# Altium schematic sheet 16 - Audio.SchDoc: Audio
size A3; PageSetup: Record=PageOptions¦CenterHorizontal=True¦CenterVertical=True¦PrintScale=0.70¦XCorrection=1.00¦YCorrection=1.00¦PrintKind=0¦BorderSize=5000000¦LeftOffset=0¦BottomOffset=0¦Orientation=2¦PaperLength=4200¦PaperWidth=2970¦Scale=100¦PaperSource=7¦PrintQuality=600¦MediaType=1¦DitherType=10¦PaperKind=A4¦PrintScaleMode=1; Author: Juan Anzola; SheetNumber: 16; SheetTotal: 20
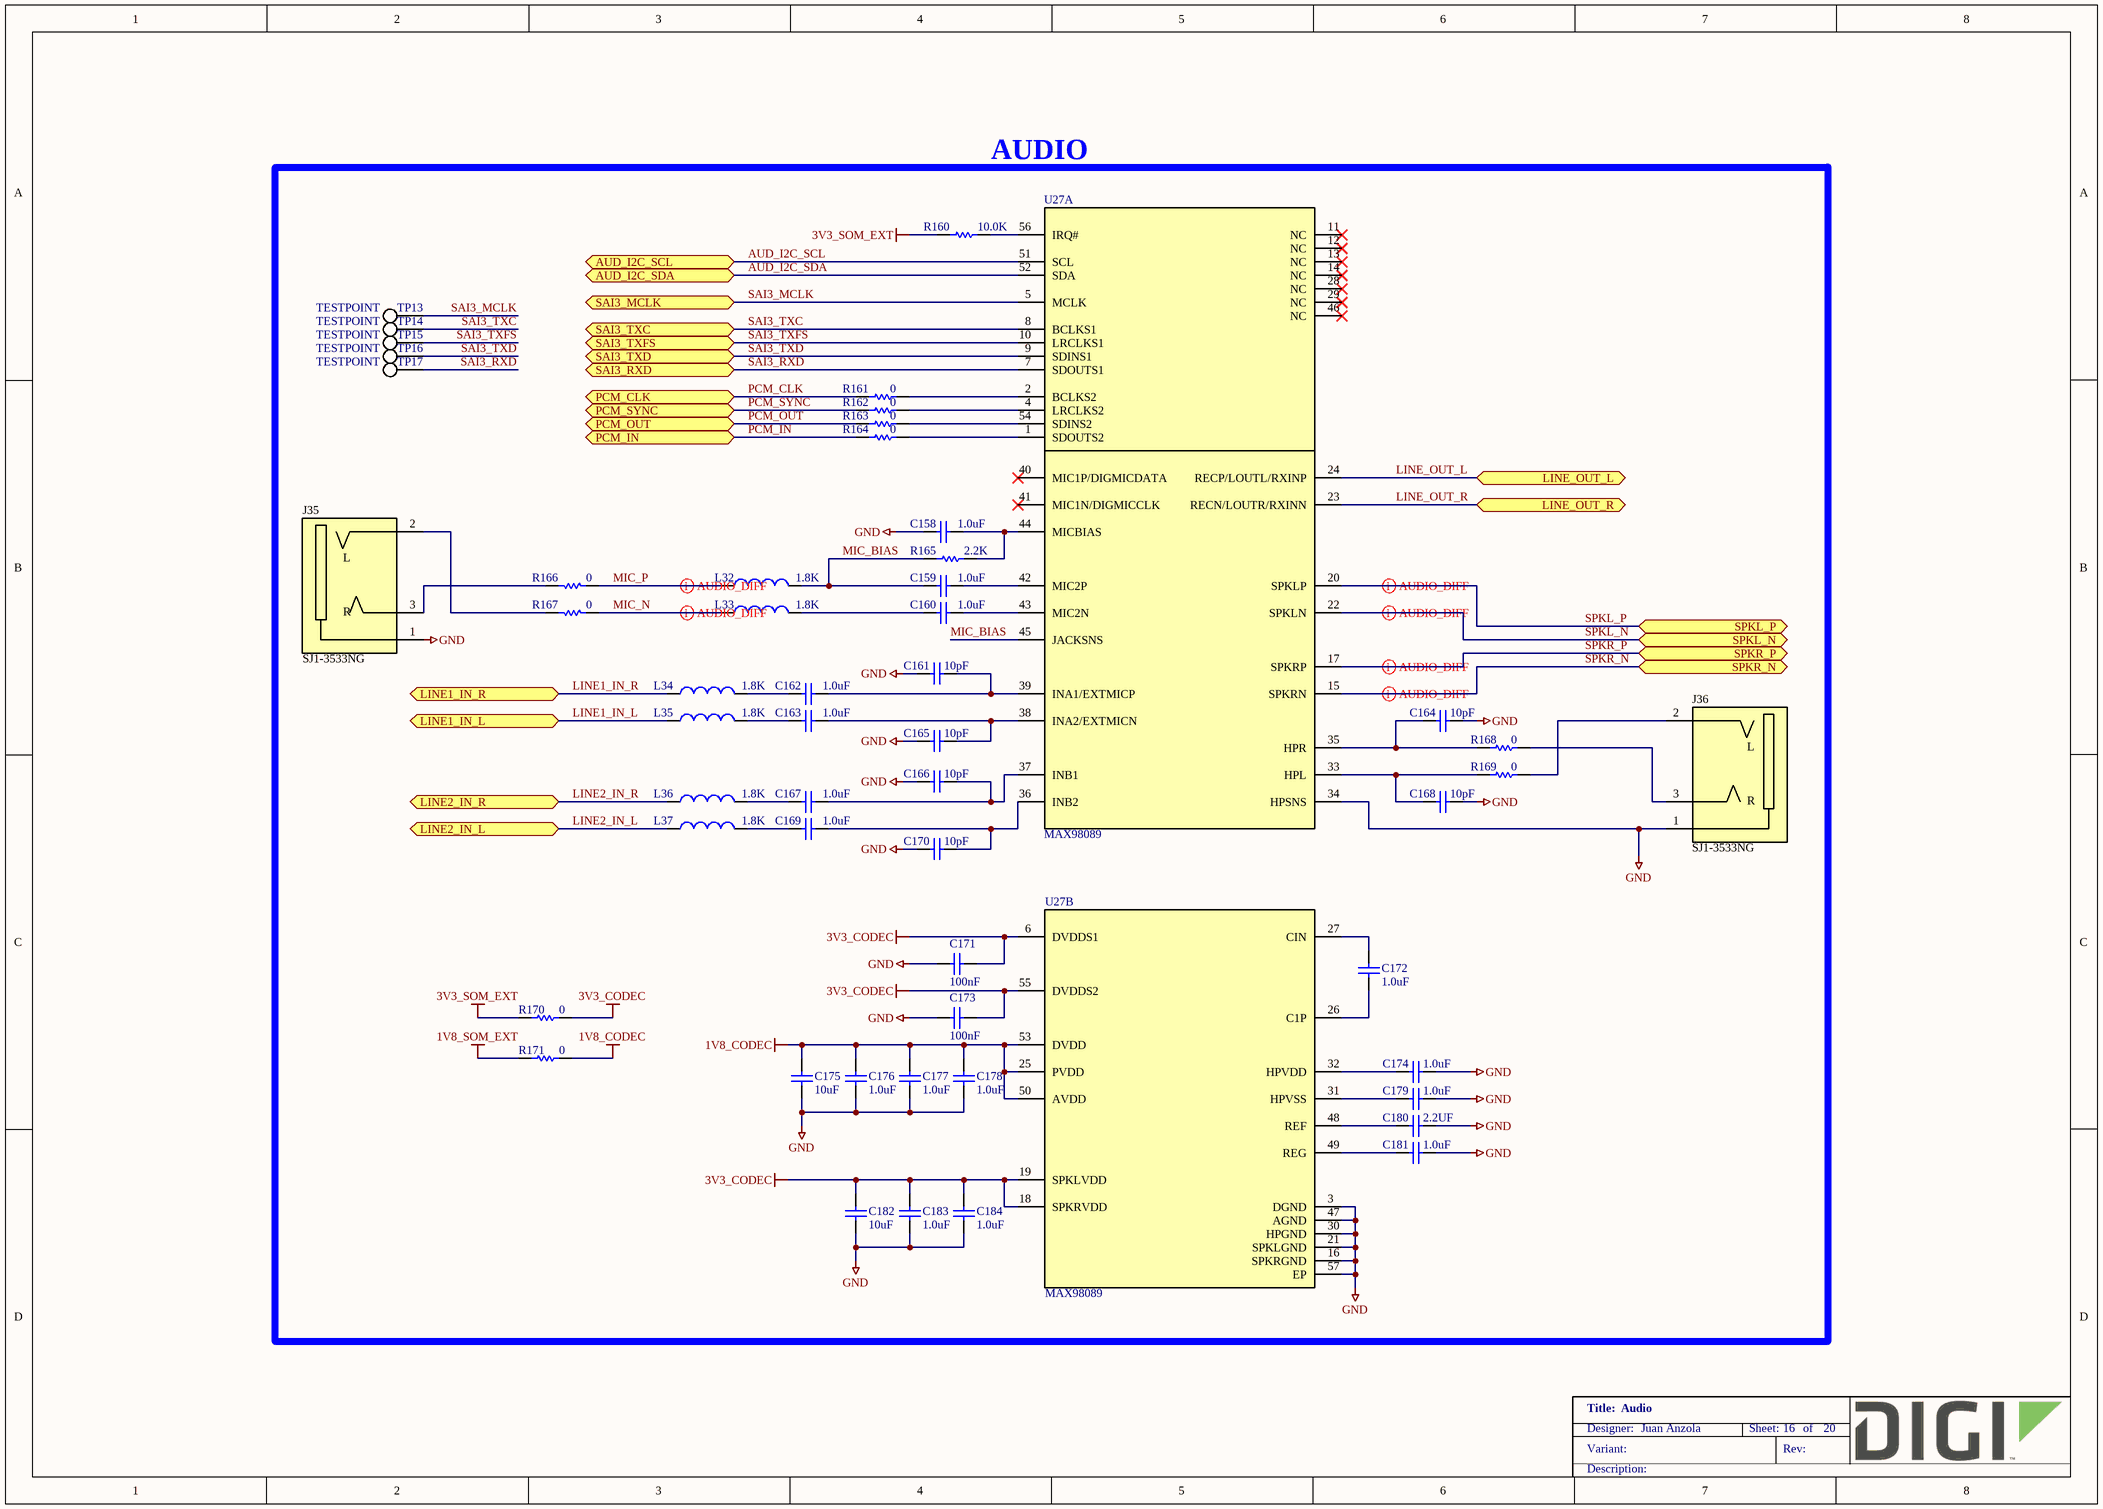
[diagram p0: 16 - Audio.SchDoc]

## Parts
C158  1.0uF  [CAPC1005X55N]
C159  1.0uF  [CAPC1005X55N]
C160  1.0uF  [CAPC1005X55N]
C161  10pF  [CAPC1005X55N]
C162  1.0uF  [CAPC1005X55N]
C163  1.0uF  [CAPC1005X55N]
C164  10pF  [CAPC1005X55N]
C165  10pF  [CAPC1005X55N]
C166  10pF  [CAPC1005X55N]
C167  1.0uF  [CAPC1005X55N]
C168  10pF  [CAPC1005X55N]
C169  1.0uF  [CAPC1005X55N]
C170  10pF  [CAPC1005X55N]
C171  100nF  [CAPC1005X55N]
C172  1.0uF  [CAPC1005X55N]
C173  100nF  [CAPC1005X55N]
C174  1.0uF  [CAPC1005X55N]
C175  10uF  [CAPC1005X55N]
C176  1.0uF  [CAPC1005X55N]
C177  1.0uF  [CAPC1005X55N]
C178  1.0uF  [CAPC1005X55N]
C179  1.0uF  [CAPC1005X55N]
C180  2.2UF  [CAPC1608X90N]
C181  1.0uF  [CAPC1005X55N]
C182  10uF  [CAPC1005X55N]
C183  1.0uF  [CAPC1005X55N]
C184  1.0uF  [CAPC1005X55N]
J35  SJ1-3533NG  [CUI_SJ1-3533N]
J36  SJ1-3533NG  [CUI_SJ1-3533N]
L32  1.8K  [INDC1005X60N]
L33  1.8K  [INDC1005X60N]
L34  1.8K  [INDC1005X60N]
L35  1.8K  [INDC1005X60N]
L36  1.8K  [INDC1005X60N]
L37  1.8K  [INDC1005X60N]
R160  10.0K  [RESC1005X40N]
R161  0  [RESC1005X40N]
R162  0  [RESC1005X40N]
R163  0  [RESC1005X40N]
R164  0  [RESC1005X40N]
R165  2.2K  [RESC1005X40N]
R166  0  [RESC1005X40N]
R167  0  [RESC1005X40N]
R168  0  [RESC1005X40N]
R169  0  [RESC1005X40N]
R170  0  [RESC1609X55N]
R171  0  [RESC1609X55N]
TP13  TESTPOINT  [TP0762]  (no BOM)
TP14  TESTPOINT  [TP0762]  (no BOM)
TP15  TESTPOINT  [TP0762]  (no BOM)
TP16  TESTPOINT  [TP0762]  (no BOM)
TP17  TESTPOINT  [TP0762]  (no BOM)
U27  MAX98089  [QFN40P700X700X80-57T560X560N]  (parts A,B of 2)

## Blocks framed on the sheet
AUDIO: C158-C184 J35 J36 L32-L37 R160-R171 TP13-TP17 U27

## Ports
AUD_I2C_SCL (bidir), AUD_I2C_SDA (bidir), LINE1_IN_L (bidir), LINE1_IN_R (bidir), LINE2_IN_L (bidir), LINE2_IN_R (bidir), LINE_OUT_L (bidir), LINE_OUT_R (bidir), PCM_CLK (bidir), PCM_IN (bidir), PCM_OUT (bidir), PCM_SYNC (bidir), SAI3_MCLK (bidir), SAI3_RXD (bidir), SAI3_TXC (bidir), SAI3_TXD (bidir), SAI3_TXFS (bidir), SPKL_N (bidir), SPKL_P (bidir), SPKR_N (bidir), SPKR_P (bidir)

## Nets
1V8_CODEC: C175.2 C176.1 C177.1 C178.1 R171.2 U27.25(PVDD) U27.50(AVDD) U27.53(DVDD)
1V8_SOM_EXT: R171.1
3V3_CODEC: C171.2 C173.2 C182.2 C183.1 C184.1 R170.2 U27.6(DVDDS1) U27.18(SPKRVDD) U27.19(SPKLVDD) U27.55(DVDDS2)
3V3_SOM_EXT: R160.1 R170.1
GND: C158.2 C161.2 C164.2 C165.2 C166.2 C168.2 C170.2 C171.1 C173.1 C174.1 C175.1 C176.2 C177.2 C178.2 C179.1 C180.1 C181.1 C182.1 C183.2 C184.2 J35.1 J36.1 U27.3(DGND) U27.16(SPKRGND) U27.21(SPKLGND) U27.30(HPGND) U27.34(HPSNS) U27.47(AGND) U27.57(EP)
AUD_I2C_SCL: U27.51(SCL) ; port AUD_I2C_SCL
AUD_I2C_SDA: U27.52(SDA) ; port AUD_I2C_SDA
LINE1_IN_L: L35.1 ; port LINE1_IN_L
LINE1_IN_R: L34.1 ; port LINE1_IN_R
LINE2_IN_L: L37.1 ; port LINE2_IN_L
LINE2_IN_R: L36.1 ; port LINE2_IN_R
LINE_OUT_L: U27.24(RECP/LOUTL/RXINP) ; port LINE_OUT_L
LINE_OUT_R: U27.23(RECN/LOUTR/RXINN) ; port LINE_OUT_R
MIC_BIAS: C159.2 L32.2 R165.1 U27.45(JACKSNS)
MIC_N: L33.1 R167.1
MIC_P: L32.1 R166.1
PCM_CLK: R161.1 ; port PCM_CLK
PCM_IN: R164.1 ; port PCM_IN
PCM_OUT: R163.1 ; port PCM_OUT
PCM_SYNC: R162.1 ; port PCM_SYNC
SAI3_MCLK: TP13.1 U27.5(MCLK) ; port SAI3_MCLK
SAI3_RXD: TP17.1 U27.7(SDOUTS1) ; port SAI3_RXD
SAI3_TXC: TP14.1 U27.8(BCLKS1) ; port SAI3_TXC
SAI3_TXD: TP16.1 U27.9(SDINS1) ; port SAI3_TXD
SAI3_TXFS: TP15.1 U27.10(LRCLKS1) ; port SAI3_TXFS
SPKL_N: U27.22(SPKLN) ; port SPKL_N
SPKL_P: U27.20(SPKLP) ; port SPKL_P
SPKR_N: U27.15(SPKRN) ; port SPKR_N
SPKR_P: U27.17(SPKRP) ; port SPKR_P
NetC158_1: C158.1 R165.2 U27.44(MICBIAS)
NetC159_1: C159.1 U27.42(MIC2P)
NetC160_1: C160.1 U27.43(MIC2N)
NetC160_2: C160.2 L33.2
NetC161_1: C161.1 C162.1 U27.39(INA1/EXTMICP)
NetC162_2: C162.2 L34.2
NetC163_1: C163.1 C165.1 U27.38(INA2/EXTMICN)
NetC163_2: C163.2 L35.2
NetC164_1: C164.1 R168.1 U27.35(HPR)
NetC166_1: C166.1 C167.1 U27.37(INB1)
NetC167_2: C167.2 L36.2
NetC168_1: C168.1 R169.1 U27.33(HPL)
NetC169_1: C169.1 C170.1 U27.36(INB2)
NetC169_2: C169.2 L37.2
NetC172_1: C172.1 U27.27(CIN)
NetC172_2: C172.2 U27.26(C1P)
NetC174_2: C174.2 U27.32(HPVDD)
NetC179_2: C179.2 U27.31(HPVSS)
NetC180_2: C180.2 U27.48(REF)
NetC181_2: C181.2 U27.49(REG)
NetJ35_2: J35.2 R167.2
NetJ35_3: J35.3 R166.2
NetJ36_2: J36.2 R169.2
NetJ36_3: J36.3 R168.2
NetR160_2: R160.2 U27.56(IRQ#)
NetR161_2: R161.2 U27.2(BCLKS2)
NetR162_2: R162.2 U27.4(LRCLKS2)
NetR163_2: R163.2 U27.54(SDINS2)
NetR164_2: R164.2 U27.1(SDOUTS2)

Not connected (* = marked no-connect by the designer): U27 11(NC)* 12(NC)* 13(NC)* 14(NC)* 28(NC)* 29(NC)* 40(MIC1P/DIGMICDATA)* 41(MIC1N/DIGMICCLK)* 46(NC)*

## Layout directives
differential pair: MIC_N, MIC_P, SPKL_N, SPKL_P, SPKR_N, SPKR_P

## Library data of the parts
C158-C160 C162 C163 C167 C169 = 1001167: CAP CER 1UF 10V 10% X5R 0402; Part_Type: Capacitor; Manufacturer: Murata; Manufacturer_Part_Number: GRM155R61A105KE15D; Digi_PN: 14050399; Component_Life_Cycle_State: Reviewed; Area: 0,95
C161 C164-C166 C168 C170 = 1001541: CAP CER 10PF 50V 5% NP0 0402; Part_Type: Capacitor; Manufacturer: Murata; Manufacturer_Part_Number: GRM1555C1H100JA01D; Note: 14050750 = Digi No. for GE WDNU; Digi_PN: 14050362; Component_Life_Cycle_State: Reviewed; Area: 0,95; Project: KITT v0.4; Tolerance: 5; Temp_Coef: C0G, NP0
C171 C173 = 1000006: CAP 100nF 16V 10% X7R 0402; Part_Type: Capacitor; Manufacturer: Murata; Manufacturer_Part_Number: GRM155R71C104KA88D; Digi_PN: 14050552; Component_Life_Cycle_State: CAD Reviewed; Area: 0.95; Project: KITT; Tolerance: 10
C172 C174 C176-C179 C181 C183 C184 = 1001167: CAP CER 1UF 10V 10% X5R 0402; Part_Type: Capacitor; Manufacturer: Murata; Manufacturer_Part_Number: GRM155R61A105KE15D; Digi_PN: 14050399; Component_Life_Cycle_State: Reviewed; Area: 0.95; Project: CCWMX6_SBC board
C175 C182 = 1001168: CAP CER 10UF 10V 20% X5R 0402; Part_Type: Capacitor; Manufacturer: Samsung; Manufacturer_Part_Number: CL05A106MP5NUNC; Digi_PN: 14050689; Component_Life_Cycle_State: Reviewed; Area: 0.95; Project: CCWMX6_SBC board
C180 = 1001303: CAP CER 2.2UF 16V 10% X5R 0603; Part_Type: Capacitor; Manufacturer: TDK Corporation; Manufacturer_Part_Number: C1608X5R1C225K080AB; Digi_PN: 14050730; Component_Life_Cycle_State: Reviewed; Area: 2,27; Project: Pinnacle
J35 J36 = 1002596: CONN JACK STEREO 3.5MM R/A; Part_Type: Connector; Manufacturer: CUI Inc.; Digi_PN: 18000594; Component_Life_Cycle_State: Reviewed; Area: 163.02; Project: CCWMX6_SBC board
L32-L37 = 1002041: FERRITE BEAD 1.8 KOHM 0402 1LN; Manufacturer: Murata; Manufacturer_Part_Number: BLM15HD182SN1D; Digi_PN: 21000461; Component_Life_Cycle_State: Reviewed; Area: 2.2; Project: iMX6UL+PMIC
R160 = 1000537: RES 10.0K OHM 1/10W 1% 0402 SMD; Part_Type: Resistor; Manufacturer: Panasonic - ECG; Manufacturer_Part_Number: ERJ-2RKF1002X; Component_Life_Cycle_State: CAD Reviewed; Area: 0.95; Project: KITT; Power_WV_SRF: 100; Digi_PN: 13051084
R161-R164 R166-R169 = 1000076: RES 0.0 OHM 1/10W 0402 SMD; Part_Type: Resistor; Manufacturer: Panasonic - ECG; Manufacturer_Part_Number: ERJ-2GE0R00X; Component_Life_Cycle_State: Proven; Area: 0.95; Project: Adjustable Foundation; Power_WV_SRF: 10; Digi_PN: 13050387
R165 = 1001156: RES 2.20K OHM 1/16W 1% 0402 SMD; Part_Type: Resistor; Manufacturer: Yageo; Manufacturer_Part_Number: RC0402FR-072K2L; Note: 13051099 = Digi No. for GE WDNU; Digi_PN: 13050699; Component_Life_Cycle_State: Reviewed; Area: 0,95; Project: CCWMX6_SBC board
R170 R171 = 1000208: RES 0.0 OHM 1/10W 0603; Part_Type: Resistor; Manufacturer: Panasonic - ECG; Manufacturer_Part_Number: ERJ-3GEY0R00V; Note: 13051103 = Digi No. for GE WDNU; Digi_PN: 13050568; Component_Life_Cycle_State: Reviewed; Area: 2.5; Project: Adjustable Foundation; Voltage: 75V
TP13-TP17 = CAD0011: TEST POINT 30MIL PAD SMT; Component_Life_Cycle_State: Reviewed; Area: 0,58; Project: CLC
U27 = 1002001: IC CODEC AUDIO FLEXSOUND 56TQFN; Manufacturer: Maxim; Manufacturer_Part_Number: MAX98089ETN+T; Component_Life_Cycle_State: Reviewed; Area: 49; Project: iMX6UL+PMIC; Digi_PN: 16052036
